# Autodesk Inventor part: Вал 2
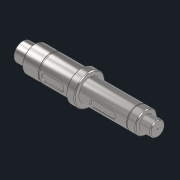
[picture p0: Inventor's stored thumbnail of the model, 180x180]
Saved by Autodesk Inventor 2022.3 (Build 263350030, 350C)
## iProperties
Created: 2022-08
Part Number: Вал 2
Material: Сталь 40ХНМА
Document SubType Name: Modeling
Designer: Карташов
Density: 7.85 g/cm^3
Appearance: С умеренной полировкой
Author: Карташов
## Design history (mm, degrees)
sketch "Эскиз1"
  geometry: L1 (0, 0)-(-371, 0); L2 (-371, 0)-(-371, 25); L3 (-371, 25)-(-337, 25); L4 (-337, 25)-(-337, 35); L5 (-293, 35)-(-293, 33.5); L6 (-289, 33.5)-(-289, 35); L7 (-209, 35)-(-209, 42); L8 (-209, 42)-(-186, 42); L9 (-186, 42)-(-186, 30); L10 (-186, 30)-(-56, 30); L11 (-56, 30)-(-56, 28.5); L12 (-53, 28.5)-(-53, 30); L13 (-53, 30)-(-31, 30); L14 (-31, 30)-(-31, 20); L15 (-31, 20)-(0, 20); L16 (0, 20)-(0, 0); L17 (-56, 28.5)-(-53, 28.5); L18 (-293, 33.5)-(-289, 33.5); L19 (-209, 35)-(-289, 35); L20 (-293, 35)-(-337, 35); C1 r 1.5 at (-0.5, 0); C2 r 1.5 at (-370.5, 0); 9 further points
  constraints: 40 end point, 6 horizontal, 5 midpoint, 5 vertical, 4 parallel, 3 perpendicular, 2 centre point, 2 horizontal alignment, 2 point on line
  dimensions: "d0" = 40 diameter of L15 L1; "d1" = 31 distance of L14.end L15.end; "d2" = 60 diameter of L10 L1; "d3" = 57 diameter of L17 L1; "d4" = 3 distance of L11.end L12.start; "d5" = 22 distance of L12.end L13.end; "d6" = 84 diameter of L8 L1; "d7" = 70 diameter of L20 L1; "d9" = 23 distance of L7.end L8.end; "d10" = 50 diameter of L3 L1; "d11" = 34 distance of L2.end L3.end; "d12" = 67 diameter of point (-291, 33.5) L1; "d13" = 4 distance of L5.end L6.start; "d14" = 44 distance of L5.start L4.end; "d15" = 128 horizontal distance of point (-209, 38.5) point (-337, 30); "d16" = 155 horizontal distance of point (-31, 25) point (-186, 36); "d17" = 3 diameter of C1; "d18" = 0.5 distance from line of L16 C1.centre; "d19" = 3 diameter of C2; "d20" = 0.5 distance from line of L2 C2.centre
revolve "Вращение1" sketch "Эскиз1" stored, may be unused: angle "d21" = 90 deg
chamfer "Фаска1" distance "d22" = 2; stored, may be unused: second distance "d23" = 2, angle "d24" = 45 deg
node "РабПлоскость1"
node "РабПлоскость2"
sketch "Эскиз2"
  geometry: L1 (-40, -35)-(-40, 35) reference; L2 (40, -35)-(40, 35) reference; L3 (-26, 0)-(17, 0); L4 (-26, -10)-(17, -10); L5 (17, 10)-(-26, 10); A1 r 10 centre (-26, 0) between (-26, 10) and (-26, -10); A2 r 10 centre (17, 0) between (17, -10) and (17, 10); 3 further points
  constraints: 8 end point, 4 point on circle, 4 tangent, 2 centre point, 2 midpoint, 1 horizontal, 1 horizontal alignment, 1 parallel
  dimensions: "d25" = 43 distance of L3.start L3.end; "d26" = 20 diameter of A2; "d27" = 23 distance from line of L2 L3.end
extrude "Выдавливание1" cut sketch "Эскиз2" distance "d28" = 4.5; taper "d29" = 0 deg
sketch "Эскиз3"
  geometry: L1 (26, 0)-(-26, 0); L2 (26, 9)-(-26, 9); L3 (-26, -9)-(26, -9); L4 (-65, 40)-(-65, -40) reference; A1 r 9 centre (26, 0) between (26, -9) and (26, 9); A2 r 9 centre (-26, 0) between (-26, 9) and (-26, -9); 4 further points
  constraints: 8 end point, 5 point on circle, 4 tangent, 2 centre point, 2 midpoint, 1 horizontal, 1 horizontal alignment, 1 parallel
  dimensions: "d30" = 52 distance of L1.start L1.end; "d31" = 18 diameter of A2; "d32" = 39 distance from line of L1.end L4
extrude "Выдавливание2" cut sketch "Эскиз3" distance "d33" = 3.4; taper "d34" = 0 deg
node "Твердое тело1"
node "Спроецированная петля1"
